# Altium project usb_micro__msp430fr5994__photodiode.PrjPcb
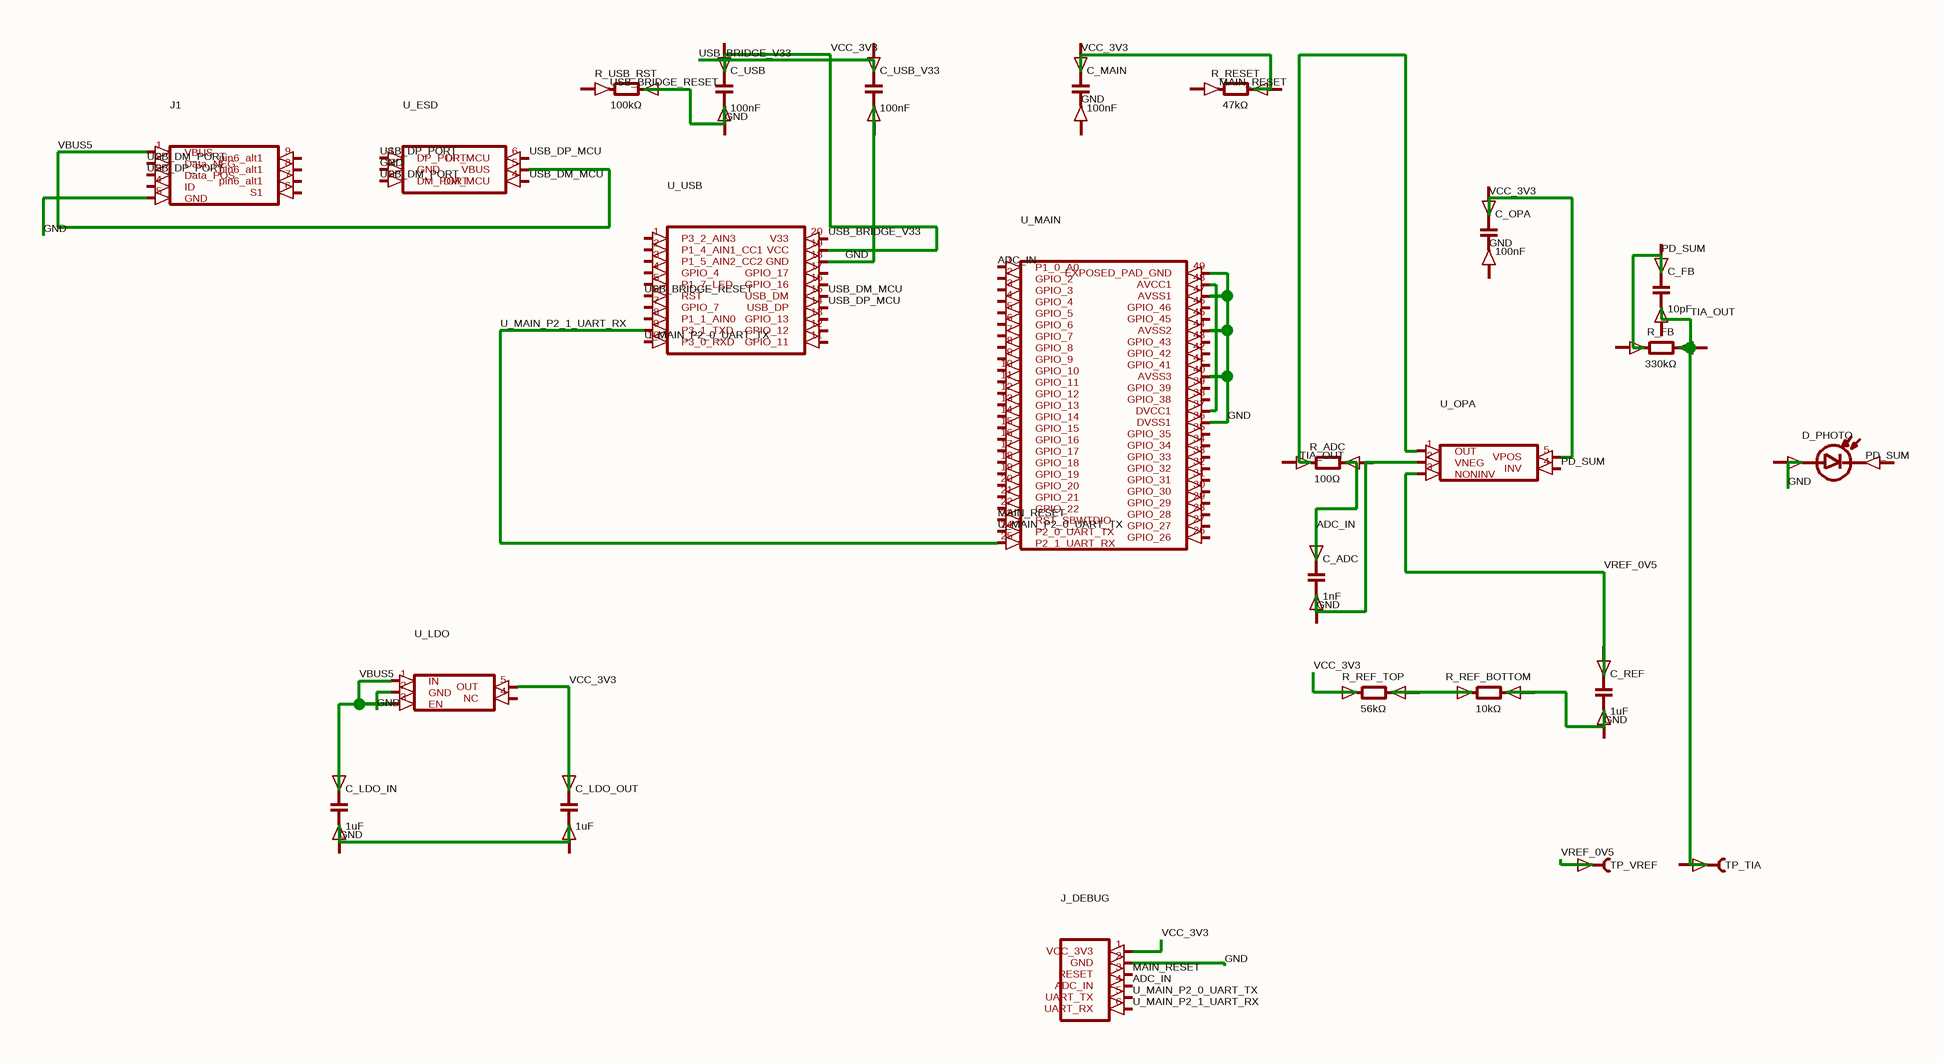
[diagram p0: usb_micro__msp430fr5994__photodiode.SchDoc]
1 sheet, 25 parts. Net scope: global (net labels, ports and power ports of the same name join across sheets).
Board file: usb_micro__msp430fr5994__photodiode.PcbDoc

## Sheet usb_micro__msp430fr5994__photodiode.SchDoc
size 213 x 135 mm

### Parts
C_ADC  1nF
C_FB  10pF
C_LDO_IN  1uF
C_LDO_OUT  1uF
C_MAIN  100nF
C_OPA  100nF
C_REF  1uF
C_USB  100nF
C_USB_V33  100nF
D_PHOTO  (no value)
J1  (no value)
J_DEBUG  (no value)
R_ADC  100Ω
R_FB  330kΩ
R_REF_BOTTOM  10kΩ
R_REF_TOP  56kΩ
R_RESET  47kΩ
R_USB_RST  100kΩ
TP_TIA  (no value)
TP_VREF  (no value)
U_ESD  (no value)
U_LDO  (no value)
U_MAIN  (no value)
U_OPA  (no value)
U_USB  (no value)

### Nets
ADC_IN: C_ADC.1(anode) J_DEBUG.4(ADC_IN) U_MAIN.1(P1_0_A0)
GND: C_USB_V33.2(cathode) J1.5(GND) J_DEBUG.2(GND) R_ADC.2(cathode) R_REF_BOTTOM.2(cathode) R_USB_RST.2(cathode) U_ESD.2(GND) U_LDO.2(GND) U_MAIN.36(DVSS1) U_MAIN.40(AVSS3) U_MAIN.44(AVSS2) U_MAIN.47(AVSS1) U_MAIN.49(EXPOSED_PAD_GND) U_OPA.2(VNEG) U_USB.18(GND)
MAIN_RESET: J_DEBUG.3(RESET) U_MAIN.23(RST_SBWTDIO)
PD_SUM: U_OPA.4(INV)
TIA_OUT: U_OPA.1(OUT)
U_MAIN_P2_0_UART_TX: J_DEBUG.5(UART_TX) U_MAIN.24(P2_0_UART_TX) U_USB.10(P3_0_RXD)
U_MAIN_P2_1_UART_RX: J_DEBUG.6(UART_RX) U_MAIN.25(P2_1_UART_RX) U_USB.9(P3_1_TXD)
USB_BRIDGE_RESET: U_USB.6(RST)
USB_BRIDGE_V33: U_USB.20(V33)
USB_DM_MCU: U_ESD.4(DM_MCU) U_USB.15(USB_DM)
USB_DM_PORT: J1.2(Data_NEG) U_ESD.3(DM_PORT)
USB_DP_MCU: U_ESD.6(DP_MCU) U_USB.14(USB_DP)
USB_DP_PORT: J1.3(Data_POS) U_ESD.1(DP_PORT)
VBUS5: C_LDO_IN.1(anode) J1.1(VBUS) U_ESD.5(VBUS) U_LDO.1(IN) U_LDO.3(EN)
VCC_3V3: C_LDO_OUT.1(anode) J_DEBUG.1(VCC_3V3) R_REF_TOP.1(anode) U_LDO.5(OUT) U_OPA.5(VPOS) U_USB.19(VCC)
VREF_0V5: C_REF.1(anode) TP_VREF.1(pin1) U_OPA.3(NONINV)
NetR_REF_BOTTOM_1: R_REF_BOTTOM.1(anode) R_REF_TOP.2(cathode)
NetU_MAIN_37: U_MAIN.37(DVCC1) U_MAIN.48(AVCC1)

Not connected (* = marked no-connect by the designer): C_ADC 2(cathode); C_FB 1(anode) 2(cathode); C_LDO_IN 2(cathode); C_LDO_OUT 2(cathode); C_MAIN 1(anode) 2(cathode); C_OPA 1(anode) 2(cathode); C_REF 2(cathode); C_USB 1(anode) 2(cathode); C_USB_V33 1(anode); D_PHOTO 1(anode) 2(cathode); J1 4(ID) 6(S1) 7(pin6_alt1) 8(pin6_alt1) 9(pin6_alt1); R_ADC 1(anode); R_FB 1(anode) 2(cathode); R_RESET 1(anode) 2(cathode); R_USB_RST 1(anode); TP_TIA 1(pin1); U_LDO 4(NC); U_MAIN 2(GPIO_2) 3(GPIO_3) 4(GPIO_4) 5(GPIO_5) 6(GPIO_6) 7(GPIO_7) 8(GPIO_8) 9(GPIO_9) 10(GPIO_10) 11(GPIO_11) 12(GPIO_12) 13(GPIO_13) 14(GPIO_14) 15(GPIO_15) 16(GPIO_16) 17(GPIO_17) 18(GPIO_18) 19(GPIO_19) 20(GPIO_20) 21(GPIO_21) 22(GPIO_22) 26(GPIO_26) 27(GPIO_27) 28(GPIO_28) 29(GPIO_29) 30(GPIO_30) 31(GPIO_31) 32(GPIO_32) 33(GPIO_33) 34(GPIO_34) 35(GPIO_35) 38(GPIO_38) 39(GPIO_39) 41(GPIO_41) 42(GPIO_42) 43(GPIO_43) 45(GPIO_45) 46(GPIO_46); U_USB 1(P3_2_AIN3) 2(P1_4_AIN1_CC1) 3(P1_5_AIN2_CC2) 4(GPIO_4) 5(P1_7_LED) 7(GPIO_7) 8(P1_1_AIN0) 11(GPIO_11) 12(GPIO_12) 13(GPIO_13) 16(GPIO_16) 17(GPIO_17)

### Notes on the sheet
- Labels drawn without touching a wire or pin: GND, MAIN_RESET, PD_SUM, USB_BRIDGE_RESET

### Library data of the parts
C_ADC C_FB C_LDO_IN C_LDO_OUT C_MAIN C_OPA C_REF C_USB C_USB_V33 = capacitor_down
D_PHOTO = photodiode_horz
J1 = J1
J_DEBUG = J_DEBUG
R_ADC R_FB R_REF_BOTTOM R_REF_TOP R_RESET R_USB_RST = boxresistor_right
TP_TIA TP_VREF = testpoint_right
U_ESD = U_ESD
U_LDO = U_LDO
U_MAIN = U_MAIN
U_OPA = U_OPA
U_USB = U_USB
